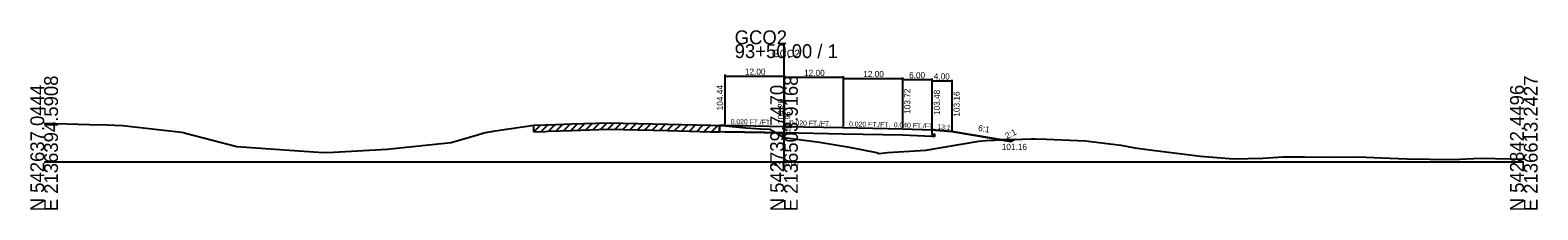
# Model space of a CAD drawing. Extents: x -14327 to 8886, y -10 to 39048.
# Drawn here: x 3997.2 to 4302.8, y 6990.3 to 7026.7 of the extents above; entities that cross this region are included whole.
import ezdxf

# ---------------------------------------------------------------- set-up
doc = ezdxf.new("R2010")
doc.units = 0
for name, color, linetype in [('Level 5', 7, 'Continuous'), ('Level 53', 7, 'Continuous'), ('Level 54', 7, 'Continuous'), ('Level 55', 7, 'Continuous'), ('Level 7', 7, 'Continuous'), ('RD_GPK_XS_Cell', 7, 'Continuous'), ('RD_XS_EwShp', 7, 'Continuous'), ('RD_XS_ExGround', 7, 'Continuous'), ('RD_XS_ExPaveRet', 7, 'Continuous'), ('RD_XS_Pave', 7, 'Continuous'), ('RD_XS_TX_Baseline', 7, 'Continuous'), ('RD_XS_TX_Elev_EX', 7, 'Continuous'), ('RD_XS_TX_Elev_PR', 7, 'Continuous'), ('RD_XS_TX_Station', 7, 'Continuous')]:
    doc.layers.add(name, color=color, linetype=linetype)

msp = doc.modelspace()

# ---------------------------------------------------------------- linework, layer by layer
at = {"layer": 'Level 5'}
for p, q in [((4136.91, 7007.36), (4136.91, 7006.02)), ((4180, 7006.48), (4180, 7005.65)), ((4138.01, 7006.11), (4136.91, 7006.02)), ((4150, 7005.87), (4138, 7006.11)), ((4138.01, 7006.11), (4150, 7005.87)), ((4162, 7005.63), (4150, 7005.87)), ((4174, 7005.39), (4162, 7005.63)), ((4180, 7005.15), (4174, 7005.39)), ((4180, 7005.65), (4180.5, 7005.63)), ((4180.5, 7005.13), (4180, 7005.15)), ((4180.5, 7005.63), (4180.5, 7005.13))]:
    msp.add_line(p, q, dxfattribs=at)
at = {"layer": 'Level 54'}
for p, q in [((4138, 7017.71), (4138, 7007.64)), ((4138, 7017.59), (4138, 7007.64)), ((4138, 7017.39), (4150, 7017.39)), ((4150, 7017.59), (4150, 7007.4)), ((4150, 7017.35), (4150, 7007.4)), ((4150, 7017.15), (4162, 7017.15)), ((4162, 7017.35), (4162, 7007.16)), ((4162, 7017.11), (4162, 7007.16)), ((4162, 7016.91), (4174, 7016.91)), ((4174, 7017.11), (4174, 7006.92)), ((4174, 7016.87), (4174, 7006.92)), ((4174, 7016.67), (4180, 7016.67)), ((4180, 7016.87), (4180, 7006.68)), ((4180, 7016.63), (4180, 7006.68)), ((4180, 7016.43), (4184, 7016.43)), ((4184, 7016.63), (4184, 7006.36))]:
    msp.add_line(p, q, dxfattribs=at)
at = {"layer": 'Level 7'}
for p, q in [((4180, 7006.48), (4184, 7006.16)), ((4184, 7006.16), (4196, 7004.16)), ((4196, 7004.16), (4196.76, 7004.54))]:
    msp.add_line(p, q, dxfattribs=at)
at = {"layer": 'RD_GPK_XS_Cell'}
for p, q in [((4150, 7000), (4150, 7023.82)), ((4000, 7000), (4150, 7000)), ((4150, 7000), (4300, 7000))]:
    msp.add_line(p, q, dxfattribs=at)
at = {"layer": 'RD_XS_EwShp'}
for points in [[(4136.91, 7007.36), (4138.13, 7007.27), (4142.23, 7006.91), (4145.32, 7006.73), (4147.16, 7006.6), (4148.35, 7005.96), (4148.44, 7005.9), (4138, 7006.11), (4136.91, 7006.02)], [(4148.44, 7005.9), (4149.87, 7004.96), (4154.64, 7004.32), (4157.17, 7004), (4162.84, 7003.07), (4168.73, 7001.88), (4169.29, 7001.72), (4170.98, 7001.93), (4178.74, 7002.36), (4189.52, 7004.18), (4191.08, 7004.34), (4192.61, 7004.42), (4194.18, 7004.46), (4184, 7006.16), (4180, 7006.48), (4180, 7005.65), (4180.5, 7005.63), (4180.5, 7005.13), (4180, 7005.15), (4174, 7005.39), (4162, 7005.63), (4150, 7005.87)], [(4194.18, 7004.46), (4196, 7004.16), (4196.76, 7004.54)]]:
    msp.add_lwpolyline(points, close=True, dxfattribs=at)
at = {"layer": 'RD_XS_ExGround'}
for p, q in [((4000, 7007.82), (4000.07, 7007.82)), ((4000.07, 7007.82), (4009.21, 7007.59)), ((4009.21, 7007.59), (4012.8, 7007.51)), ((4012.8, 7007.51), (4014.27, 7007.45)), ((4014.27, 7007.45), (4015.92, 7007.38)), ((4015.92, 7007.38), (4020.68, 7006.8)), ((4020.68, 7006.8), (4027.83, 7006.02)), ((4089.13, 7005.91), (4091.44, 7006.26)), ((4091.44, 7006.26), (4099.28, 7007.41)), ((4099.28, 7007.41), (4101.58, 7007.49)), ((4101.58, 7007.49), (4102.11, 7007.51)), ((4102.11, 7007.51), (4107.01, 7007.68)), ((4107.01, 7007.68), (4114.3, 7007.94)), ((4114.3, 7007.94), (4117.37, 7007.87)), ((4117.37, 7007.87), (4126.38, 7007.67)), ((4126.38, 7007.67), (4135.16, 7007.41)), ((4135.16, 7007.41), (4136.91, 7007.36)), ((4136.91, 7007.36), (4138.13, 7007.27)), ((4138.13, 7007.27), (4142.23, 7006.91)), ((4142.23, 7006.91), (4145.32, 7006.73)), ((4145.32, 7006.73), (4147.16, 7006.6)), ((4147.16, 7006.6), (4148.35, 7005.96)), ((4027.83, 7006.02), (4028.26, 7005.94)), ((4028.26, 7005.94), (4028.66, 7005.81)), ((4028.66, 7005.81), (4033.83, 7004.5)), ((4033.83, 7004.5), (4039.06, 7003.15)), ((4069.57, 7002.58), (4078.59, 7003.51)), ((4078.59, 7003.51), (4082.5, 7003.94)), ((4082.5, 7003.94), (4087.83, 7005.49)), ((4087.83, 7005.49), (4088.74, 7005.77)), ((4088.74, 7005.77), (4089.13, 7005.91)), ((4148.35, 7005.96), (4149.87, 7004.96)), ((4149.87, 7004.96), (4154.64, 7004.32)), ((4154.64, 7004.32), (4157.17, 7004)), ((4157.17, 7004), (4162.84, 7003.07)), ((4178.74, 7002.36), (4189.52, 7004.18)), ((4189.52, 7004.18), (4191.08, 7004.34)), ((4191.08, 7004.34), (4192.61, 7004.42)), ((4192.61, 7004.42), (4200.21, 7004.64)), ((4200.21, 7004.64), (4200.93, 7004.7)), ((4200.93, 7004.7), (4203.25, 7004.59)), ((4203.25, 7004.59), (4211.1, 7004.28)), ((4211.1, 7004.28), (4218.31, 7003.37)), ((4218.31, 7003.37), (4221.11, 7002.82)), ((4039.06, 7003.15), (4051.63, 7002.21)), ((4051.63, 7002.21), (4056.61, 7001.88)), ((4056.61, 7001.88), (4058.68, 7001.96)), ((4058.68, 7001.96), (4069.57, 7002.58)), ((4162.84, 7003.07), (4168.73, 7001.88)), ((4168.73, 7001.88), (4169.29, 7001.72)), ((4169.29, 7001.72), (4170.98, 7001.93)), ((4170.98, 7001.93), (4178.74, 7002.36)), ((4221.11, 7002.82), (4224.14, 7002.46)), ((4224.14, 7002.46), (4234.42, 7001.15)), ((4234.42, 7001.15), (4241.13, 7000.6)), ((4241.13, 7000.6), (4247.06, 7000.76)), ((4247.06, 7000.76), (4251.14, 7001.05)), ((4251.14, 7001.05), (4255.56, 7001.06)), ((4255.56, 7001.06), (4261.15, 7000.99)), ((4261.15, 7000.99), (4266.5, 7001.02)), ((4266.5, 7001.02), (4271.16, 7000.85)), ((4271.16, 7000.85), (4276.28, 7000.64)), ((4276.28, 7000.64), (4285.61, 7000.52)), ((4285.61, 7000.52), (4291.18, 7000.73)), ((4291.18, 7000.73), (4297.22, 7000.61)), ((4297.22, 7000.61), (4300, 7000.55))]:
    msp.add_line(p, q, dxfattribs=at)
at = {"layer": 'RD_XS_ExPaveRet'}
for p, q in [((4099.28, 7006.11), (4100.62, 7007.46)), ((4099.28, 7006.11), (4099.28, 7007.41)), ((4100.78, 7006.16), (4102.12, 7007.51)), ((4102.11, 7006.21), (4107.01, 7006.38)), ((4102.28, 7006.21), (4103.63, 7007.56)), ((4103.78, 7006.27), (4105.13, 7007.61)), ((4105.28, 7006.32), (4106.63, 7007.67)), ((4106.78, 7006.37), (4108.13, 7007.72)), ((4107.01, 7006.38), (4114.3, 7006.64)), ((4108.28, 7006.43), (4109.63, 7007.77)), ((4109.79, 7006.48), (4111.14, 7007.83)), ((4111.29, 7006.53), (4112.64, 7007.88)), ((4112.79, 7006.59), (4114.14, 7007.93)), ((4114.29, 7006.64), (4115.56, 7007.91)), ((4114.3, 7006.64), (4117.37, 7006.57)), ((4115.79, 7006.61), (4117.07, 7007.88)), ((4117.29, 7006.57), (4118.57, 7007.85)), ((4117.37, 7006.57), (4126.38, 7006.37)), ((4118.8, 7006.54), (4120.07, 7007.81)), ((4120.3, 7006.51), (4121.57, 7007.78)), ((4121.8, 7006.47), (4123.07, 7007.75)), ((4123.3, 7006.44), (4124.57, 7007.71)), ((4124.8, 7006.41), (4126.07, 7007.68)), ((4126.3, 7006.37), (4127.57, 7007.64)), ((4126.38, 7006.37), (4135.16, 7006.11)), ((4127.8, 7006.33), (4129.07, 7007.59)), ((4129.31, 7006.28), (4130.57, 7007.55)), ((4130.81, 7006.24), (4132.07, 7007.5)), ((4132.31, 7006.19), (4133.57, 7007.46)), ((4133.81, 7006.15), (4135.07, 7007.41)), ((4135.31, 7006.1), (4136.58, 7007.37)), ((4136.91, 7007.36), (4136.91, 7006.06)), ((4099.28, 7006.11), (4101.58, 7006.19)), ((4101.58, 7006.19), (4102.11, 7006.21)), ((4135.16, 7006.11), (4136.91, 7006.06))]:
    msp.add_line(p, q, dxfattribs=at)
at = {"layer": 'RD_XS_Pave'}
for p, q in [((4138, 7007.44), (4136.91, 7007.36)), ((4138, 7007.44), (4150, 7007.2)), ((4150, 7007.2), (4162, 7006.96)), ((4162, 7006.96), (4174, 7006.72)), ((4174, 7006.72), (4180, 7006.48))]:
    msp.add_line(p, q, dxfattribs=at)

# ---------------------------------------------------------------- texts
at = {"layer": 'Level 53'}
for s, rotation, p in [('104.44', 90, (4137.63, 7010.44)), ('103.72', 90, (4175.63, 7009.72)), ('103.48', 90, (4181.63, 7009.48)), ('103.16', 90, (4185.63, 7009.16)), ('6:1', 350.5377, (4189.3, 7006.29))]:
    msp.add_text(s, height=1.25, rotation=rotation, dxfattribs=at).set_placement(p)
msp.add_text('101.16', height=1.25, dxfattribs=at).set_placement((4194.15, 7002.41))
at = {"layer": 'Level 54'}
for s, p in [('12.00', (4142.07, 7017.64)), ('12.00', (4154.07, 7017.4)), ('12.00', (4166.07, 7017.16)), ('6.00', (4175.37, 7016.92)), ('4.00', (4180.37, 7016.68))]:
    msp.add_text(s, height=1.25, dxfattribs=at).set_placement(p)
at = {"layer": 'Level 55'}
for s, height, rotation, p in [('0.020 FT./FT.', 1, 358.8542, (4139.18, 7007.67)), ('0.020 FT./FT.', 1, 358.8542, (4151.18, 7007.43)), ('0.020 FT./FT.', 1, 358.8542, (4163.18, 7007.19)), ('0.040 FT./FT.', 1, 357.7094, (4172.24, 7007.04)), ('13:1', 1, 355.4261, (4181.07, 7006.65)), ('2:1', 1.25, 26.5651, (4195.2, 7004.6))]:
    msp.add_text(s, height=height, rotation=rotation, dxfattribs=at).set_placement(p)
at = {"layer": 'RD_GPK_XS_Cell'}
for s, p in [('GCO2', (4140, 7023.82)), ('93+50.00 / 1', (4140, 7021.02))]:
    msp.add_text(s, height=2.8, dxfattribs=at).set_placement(p)
for s, p in [('N 542637.0444', (4000, 6990)), ('E 2136394.5908', (4002.8, 6990)), ('N 542739.7470', (4150, 6990)), ('E 2136503.9168', (4152.8, 6990)), ('N 542842.4496', (4300, 6990)), ('E 2136613.2427', (4302.8, 6990))]:
    msp.add_text(s, height=2.8, rotation=90, dxfattribs=at).set_placement(p)
at = {"layer": 'RD_XS_TX_Baseline'}
msp.add_text('GCO2', height=1.5, dxfattribs=at).set_placement((4147.55, 7021.2))
at = {"layer": 'RD_XS_TX_Elev_EX'}
msp.add_text('101.95', height=1, rotation=90, dxfattribs=at).set_placement((4151.25, 7005.95))
at = {"layer": 'RD_XS_TX_Elev_PR'}
msp.add_text(' 104.20', height=1.25, rotation=90, dxfattribs=at).set_placement((4150, 7007.2))
at = {"layer": 'RD_XS_TX_Station'}
msp.add_text('93+50.00', height=1, dxfattribs=at).set_placement((4147.15, 6999.2))

doc.saveas('drawing.dxf')
